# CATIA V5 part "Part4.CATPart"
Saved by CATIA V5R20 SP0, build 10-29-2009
Part number: Part1.2
Bounding box of the stored display mesh (mm): x -15.011 to 15.011, y -13 to 13, z 0 to 6
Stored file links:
  C:\Users\Ehsan Fathi\Desktop\New folder\Assembly Design No.28\Part4.CATPart
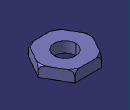
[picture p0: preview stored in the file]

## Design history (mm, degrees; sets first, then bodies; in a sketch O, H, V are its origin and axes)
Body1 (main body)
  Sketch1 on xy-plane, origin (0, 0, 0), H (1, 0, 0), V (0, 1, 0)
    line L1 (7.5056, 13) -> (0, 13)
    line L2 (-7.5056, 13) -> (-11.2583, 6.5)
    line L3 (-15.0111, 0) -> (-11.2583, -6.5)
    line L4 (-7.5056, -13) -> (0, -13)
    line L5 (7.5056, -13) -> (11.2583, -6.5)
    line L6 (15.0111, 0) -> (11.2583, 6.5)
    construction line L7 (0, 0) -> (0, 13)
    circle A1 centre (0, 0) radius 6
    arc A2 centre (0, 0) radius 13 from (-11.2583, -6.5) to (0, -13) ccw
    line L8 (0, -13) -> (7.5056, -13)
    line L9 (11.2583, -6.5) -> (15.0111, 0)
    point P10 (11.2583, 6.5)
    line L10 (11.2583, 6.5) -> (7.5056, 13)
    line L11 (0, 13) -> (-7.5056, 13)
    point P12 (-11.2583, 6.5)
    line L12 (-11.2583, 6.5) -> (-15.0111, 0)
    line L13 (-11.2583, -6.5) -> (-7.5056, -13)
    arc A3 centre (0, 0) radius 13 from (0, -13) to (11.2583, -6.5) ccw
    arc A4 centre (0, 0) radius 13 from (11.2583, -6.5) to (11.2583, 6.5) ccw
    point P15 (11.2583, 6.5)
    arc A5 centre (0, 0) radius 13 from (11.2583, 6.5) to (0, 13) ccw
    arc A6 centre (0, 0) radius 13 from (0, 13) to (-11.2583, 6.5) ccw
    point P16 (-11.2583, 6.5)
    arc A7 centre (0, 0) radius 13 from (-11.2583, 6.5) to (-11.2583, -6.5) ccw
    coincidence: P10 P15, P12 P16
  MultiPad1: profile Sketch1, domains (length 6; length 6; length 6; length 6; length 6; length 6; length 6; length 0)
  Sketch2 on face of MultiPad1, origin (11.2583, 6.5, 0), H (-0.5, 0.866, 0), V (0, 0, 1)
    arc A1 centre (4.5056, 3) radius 3 from (7.5056, 3) to (4.5056, 6) ccw
    line L1 (4.5056, 6) -> (11.2843, 10.7357)
    line L2 (11.2843, 10.7357) -> (7.5056, 3)
  Groove1: profile Sketch2, axis axis of face of MultiPad1 from Sketch1.A1, angle 360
